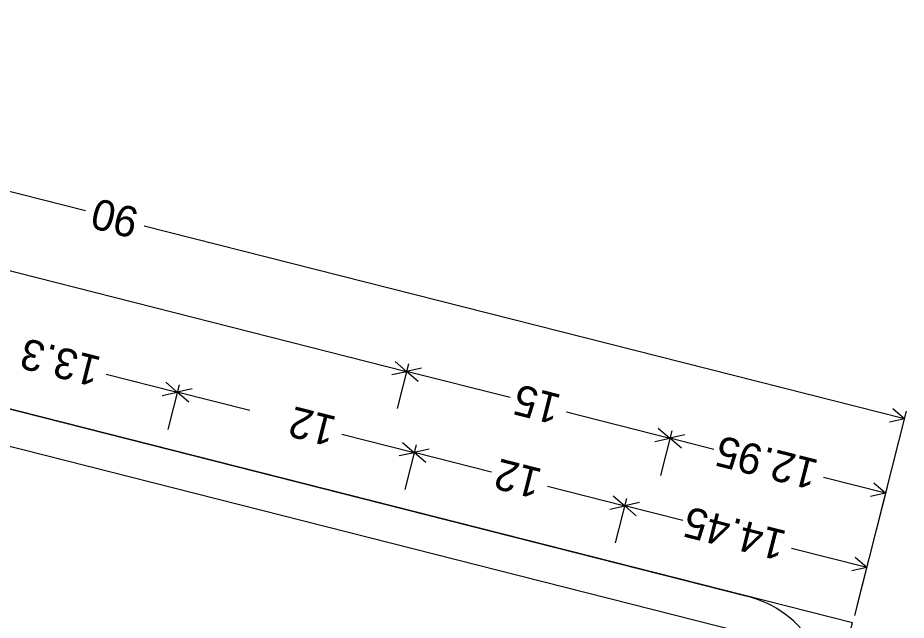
# Model space of a CAD drawing. Extents: x 670257 to 671518, y 737783 to 738188.
# Drawn here: x 671441.92 to 671449.08, y 737880.25 to 737885.1 of the extents above; entities that cross this region are included whole.
import ezdxf

# ---------------------------------------------------------------- set-up
doc = ezdxf.new("R2010")
doc.units = 0
doc.layers.add('R_SIGN', color=7, linetype='Continuous')

msp = doc.modelspace()

# ---------------------------------------------------------------- linework, layer by layer
at = {"layer": 'R_SIGN'}
for p, q in [((671442.4641, 737883.546), (671436.34, 737885.0992)), ((671442.9382, 737883.4257), (671449.0622, 737881.8725)), ((671441.1759, 737883.2358), (671445.0525, 737882.2526)), ((671444.9591, 737882.3334), (671445.0525, 737882.2526)), ((671445.0677, 737882.3126), (671444.9767, 737881.9535)), ((671445.1731, 737882.2791), (671445.0525, 737882.2526)), ((671442.6327, 737882.2297), (671443.2045, 737882.0846)), ((671444.932, 737882.2263), (671445.0525, 737882.2526)), ((671445.8863, 737882.0412), (671445.0525, 737882.2526)), ((671445.146, 737882.1721), (671445.0525, 737882.2526)), ((671443.1111, 737882.1653), (671443.2045, 737882.0846)), ((671443.2197, 737882.1444), (671443.1286, 737881.7855)), ((671443.084, 737882.0583), (671443.2045, 737882.0846)), ((671443.3251, 737882.1111), (671443.2045, 737882.0846)), ((671443.7882, 737881.9366), (671443.2045, 737882.0846)), ((671443.298, 737882.0041), (671443.2045, 737882.0846)), ((671446.3392, 737881.9263), (671447.1729, 737881.7149)), ((671449.0774, 737881.9323), (671448.6601, 737880.2871)), ((671448.9688, 737881.9531), (671449.0622, 737881.8725)), ((671448.9416, 737881.8461), (671449.0622, 737881.8725)), ((671447.0795, 737881.7956), (671447.1729, 737881.7149)), ((671447.1881, 737881.7748), (671447.097, 737881.4158)), ((671447.1881, 737881.7748), (671447.097, 737881.4158)), ((671444.5293, 737881.7486), (671445.1128, 737881.6006)), ((671447.0523, 737881.6886), (671447.1729, 737881.7149)), ((671447.2935, 737881.7413), (671447.1729, 737881.7149)), ((671447.5277, 737881.6249), (671447.1729, 737881.7149)), ((671447.2664, 737881.6343), (671447.1729, 737881.7149)), ((671445.0194, 737881.6814), (671445.1128, 737881.6006)), ((671445.128, 737881.6604), (671445.037, 737881.3015)), ((671445.2334, 737881.6271), (671445.1128, 737881.6006)), ((671444.9923, 737881.5743), (671445.1128, 737881.6006)), ((671445.7358, 737881.4426), (671445.1128, 737881.6006)), ((671445.2063, 737881.5201), (671445.1128, 737881.6006)), ((671448.4122, 737881.4006), (671448.9105, 737881.2742)), ((671448.817, 737881.3549), (671448.9105, 737881.2742)), ((671448.9257, 737881.3341), (671448.8346, 737880.9751)), ((671446.1862, 737881.3284), (671446.8091, 737881.1704)), ((671448.7899, 737881.2479), (671448.9105, 737881.2742)), ((671446.7157, 737881.2511), (671446.8091, 737881.1704)), ((671446.8243, 737881.2302), (671446.7333, 737880.8713)), ((671446.8243, 737881.2302), (671446.7333, 737880.8713)), ((671446.9297, 737881.1969), (671446.8091, 737881.1704)), ((671446.6886, 737881.1441), (671446.8091, 737881.1704)), ((671447.2765, 737881.0519), (671446.8091, 737881.1704)), ((671446.9026, 737881.0898), (671446.8091, 737881.1704)), ((671448.1544, 737880.8292), (671448.7587, 737880.676)), ((671448.6653, 737880.7567), (671448.7587, 737880.676)), ((671448.7739, 737880.7357), (671448.6829, 737880.3768)), ((671448.6382, 737880.6497), (671448.7587, 737880.676))]:
    msp.add_line(p, q, dxfattribs=at)
for points in [[(671442.1917, 737854.7829), (671448.6449, 737880.2273), (671435.9227, 737883.4539), (671429.4695, 737858.0095), (671442.1917, 737854.7829), (671442.1917, 737854.7829)], [(671436.7709, 737883.2388), (671447.7968, 737880.4424)], [(671447.7251, 737880.1597), (671436.6992, 737882.9561)]]:
    msp.add_lwpolyline(points, dxfattribs=at)
msp.add_arc((671447.5817, 737879.5942), 0.875, 345.76861, 75.76882, dxfattribs=at)

# ---------------------------------------------------------------- texts
for s, height, rotation, p in [('90', 0.24688, 165.76876, (671442.9087, 737883.5605)), ('13.3', 0.24688, 165.76876, (671442.6033, 737882.3646)), ('15', 0.24688, 165.76876, (671446.3097, 737882.0612)), ('12', 0.24688, 165.76876, (671444.4997, 737881.8836)), ('12.95', 0.24688, 165.76876, (671448.3828, 737881.5355)), ('12', 0.24688, 165.76876, (671446.1567, 737881.4633)), ('14.45', 0.24688, 165.76876, (671448.125, 737880.9641)), ('r', 1.9444, 75.76855, (671442.4681, 737879.196))]:
    msp.add_text(s, height=height, rotation=rotation, dxfattribs=at).set_placement(p)

doc.saveas('drawing.dxf')
